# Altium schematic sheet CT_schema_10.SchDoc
size 281 x 153 mm
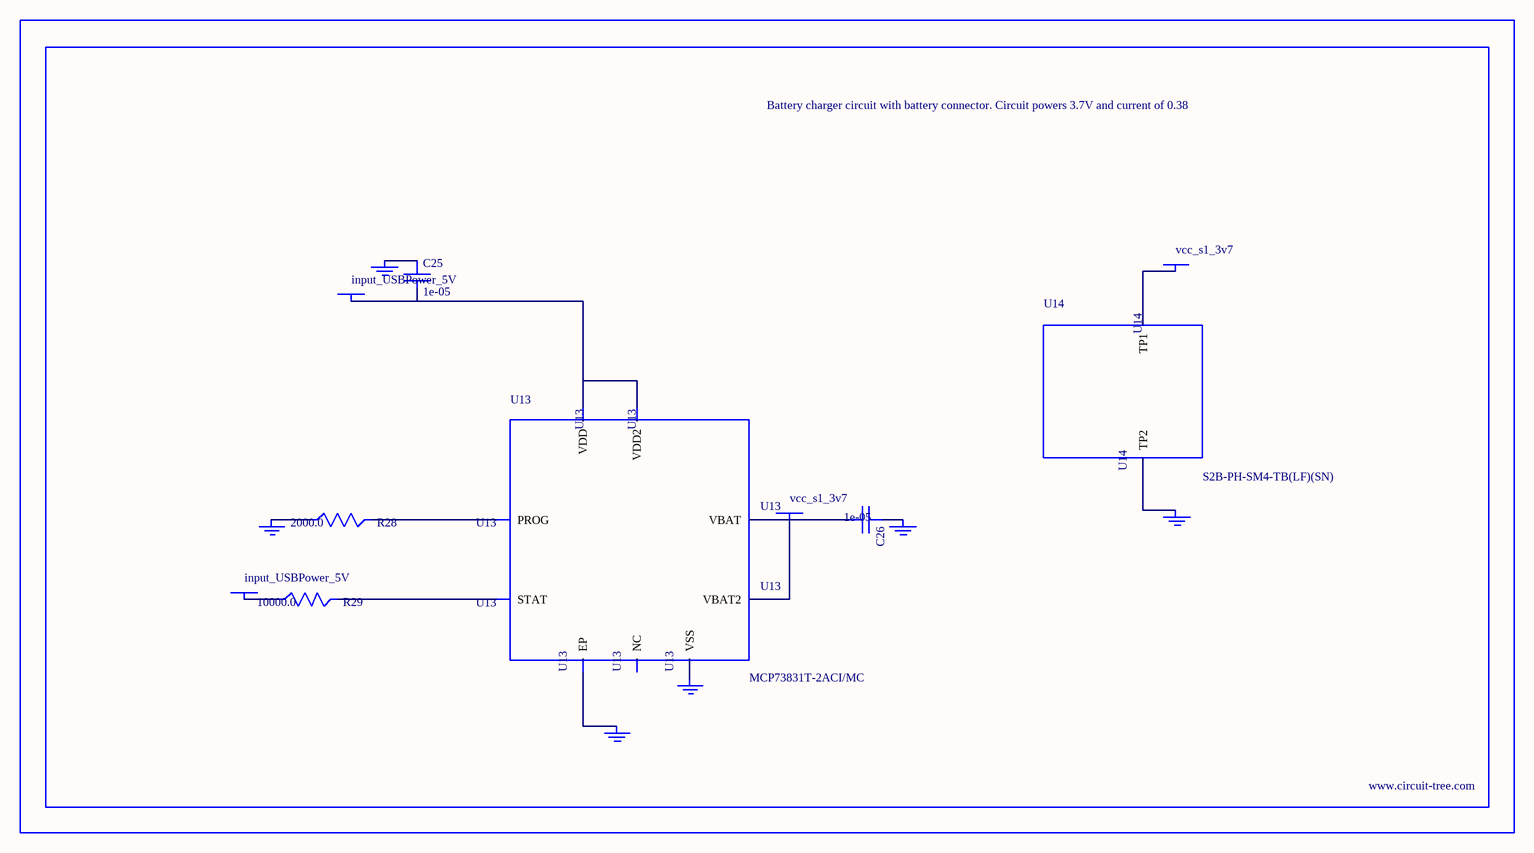
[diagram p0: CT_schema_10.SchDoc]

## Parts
BORDER9  (no value)
C25  1e-05  [C1206]
C26  1e-05  [C1206]
GND_INSTANCE_9_0  (no value)
GND_INSTANCE_9_1  (no value)
GND_INSTANCE_9_2  (no value)
GND_INSTANCE_9_3  (no value)
GND_INSTANCE_9_4  (no value)
GND_INSTANCE_9_5  (no value)
POWER_INSTANCE_9_0  input_USBPower_5V
POWER_INSTANCE_9_1  input_USBPower_5V
POWER_INSTANCE_9_2  vcc_s1_3v7
POWER_INSTANCE_9_3  vcc_s1_3v7
R28  2000.0  [R0603]
R29  10000.0  [R0603]
U13  MCP73831T-2ACI/MC  [DFN8_2X3MC]
U14  S2B-PH-SM4-TB(LF)(SN)  [JST-2-SMD]

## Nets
NetC25_1: C25.1 GND_INSTANCE_9_0.0(GND)
NetC25_2: C25.2 POWER_INSTANCE_9_0.0(PWR) U13.1(VDD) U13.2(VDD2)
NetC26_1: C26.1 GND_INSTANCE_9_1.0(GND)
NetC26_2: C26.2 POWER_INSTANCE_9_2.0(PWR) U13.3(VBAT) U13.4(VBAT2)
NetGND_INSTANCE_9_2_0: GND_INSTANCE_9_2.0(GND) R28.1
NetGND_INSTANCE_9_3_0: GND_INSTANCE_9_3.0(GND) U13.9(EP)
NetGND_INSTANCE_9_4_0: GND_INSTANCE_9_4.0(GND) U13.6(VSS)
NetGND_INSTANCE_9_5_0: GND_INSTANCE_9_5.0(GND) U14.2(TP2)
NetPOWER_INSTANCE_9_1_0: POWER_INSTANCE_9_1.0(PWR) R29.1
NetPOWER_INSTANCE_9_3_0: POWER_INSTANCE_9_3.0(PWR) U14.1(TP1)
NetR28_2: R28.2 U13.8(PROG)
NetR29_2: R29.2 U13.5(STAT)

Not connected (* = marked no-connect by the designer): U13 7(NC)

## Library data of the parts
BORDER9 = BORDER_PAGE9
C25 C26 = C1206C106K3RACTU
GND_INSTANCE_9_0-GND_INSTANCE_9_5 = GND
POWER_INSTANCE_9_0-POWER_INSTANCE_9_3 = PWR
R28 = RC0603JR-072KL
R29 = RC0603JR-0710KL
